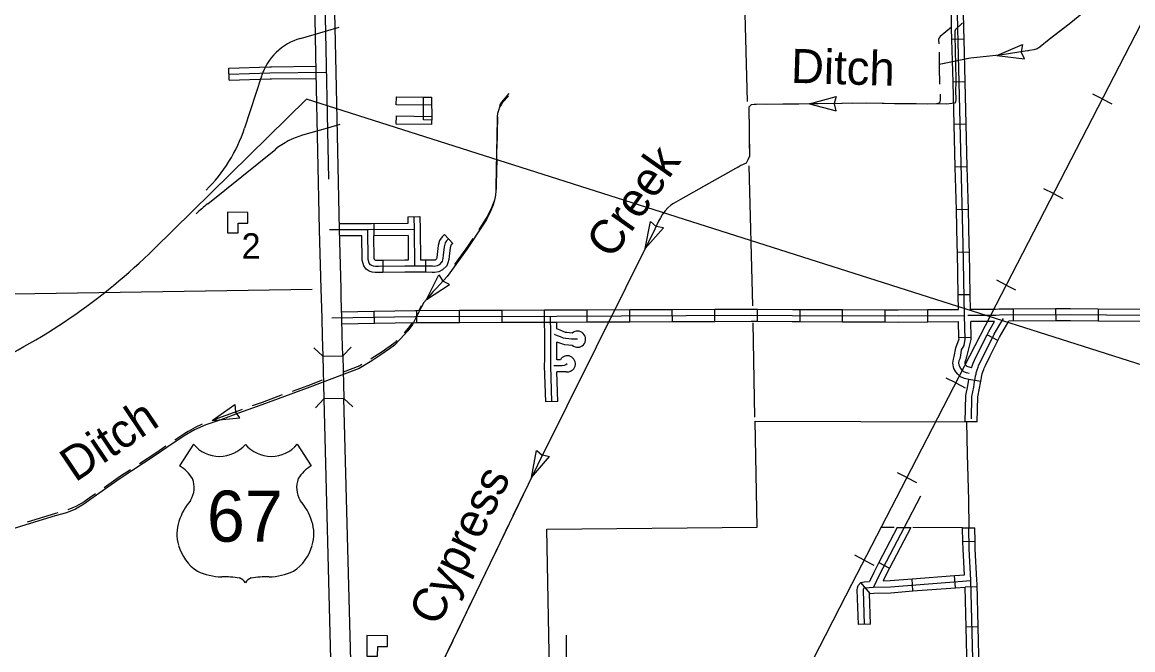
# Model space of a CAD drawing. Extents: x 1164457 to 1439835, y 1590918 to 1773502.
# Drawn here: x 1294282 to 1308056, y 1641151 to 1648927 of the extents above; entities that cross this region are included whole.
import ezdxf

# ---------------------------------------------------------------- set-up
doc = ezdxf.new("R2010")
doc.units = 0
for name, color, linetype in [('Level 10', 7, 'Continuous'), ('Level 15', 7, 'Continuous'), ('Level 22', 7, 'Continuous'), ('Level 32', 7, 'Continuous'), ('Level 34', 7, 'Continuous'), ('Level 37', 7, 'Continuous'), ('Level 40', 7, 'Continuous'), ('Level 43', 7, 'Continuous'), ('Level 45', 7, 'Continuous'), ('Level 5', 7, 'Continuous'), ('Level 58', 7, 'Continuous'), ('Level 6', 7, 'Continuous'), ('R_Draft', 7, 'Continuous')]:
    doc.layers.add(name, color=color, linetype=linetype)

msp = doc.modelspace()

# ---------------------------------------------------------------- linework, layer by layer
at = {"layer": 'Level 10'}
for points in [[(1298921, 1647904), (1298923, 1648004), (1299360, 1647997), (1299359, 1647897)], [(1299260, 1647999), (1299360, 1647997), (1299361, 1647714), (1299261, 1647716)], [(1298921, 1647665), (1298923, 1647765), (1299361, 1647758), (1299359, 1647658)]]:
    msp.add_lwpolyline(points, close=True, dxfattribs=at)
at = {"layer": 'Level 15'}
for points in [[(1297902, 1649429), (1297926, 1648305), (1297967, 1646353), (1297988, 1645622), (1297989, 1645504), (1297997, 1645260), (1298002, 1645032), (1298009, 1644787), (1298259, 1644793)], [(1298259, 1644793), (1298252, 1645039), (1298247, 1645267), (1298239, 1645510), (1298238, 1645628), (1298217, 1646359), (1298176, 1648310), (1298152, 1649429)], [(1298009, 1644787), (1298022, 1644259)], [(1298259, 1644793), (1298272, 1644266)], [(1298377, 1640272), (1298373, 1640395), (1298272, 1644266), (1298022, 1644259)], [(1298022, 1644259), (1298123, 1640389), (1298127, 1640265), (1298377, 1640272)]]:
    msp.add_lwpolyline(points, dxfattribs=at)
at = {"layer": 'Level 22'}
for p, q in [((1296407, 1643697), (1296234, 1643430)), ((1297694, 1643697), (1297867, 1643430))]:
    msp.add_line(p, q, dxfattribs=at)
for centre, radius, start, end in [((1296729, 1643968), 421, 220.075, 319.6701), ((1297371, 1643968), 421, 220.3299, 319.925), ((1296008, 1643041), 450, 30.7809, 59.7993), ((1298093, 1643041), 450, 120.2008, 149.2191), ((1296107, 1643160), 308, 328.8105, 21.2108), ((1297994, 1643160), 308, 158.7892, 211.1895), ((1296913, 1642528), 719, 138.9565, 162.6913), ((1297188, 1642528), 719, 17.3087, 41.0435), ((1296675, 1642587), 475, 160.9576, 197.3819), ((1297425, 1642587), 475, 342.6181, 19.0424), ((1296753, 1642588), 550, 195.1074, 237.1312), ((1297348, 1642588), 550, 302.8688, 344.8926), ((1296763, 1642761), 706, 244.0771, 269.5779), ((1296779, 1640762), 1293, 81.1942, 90.9539), ((1296941, 1641922), 124, 28.0342, 72.9864), ((1297160, 1641922), 124, 107.0136, 151.9658), ((1297321, 1640762), 1293, 89.0461, 98.8058), ((1297338, 1642761), 706, 270.4221, 295.9229)]:
    msp.add_arc(centre, radius, start, end, dxfattribs=at)
at = {"layer": 'Level 32'}
for p, q in [((1305964, 1648717), (1305814, 1648713)), ((1305977, 1648189), (1305827, 1648186)), ((1305991, 1647662), (1305841, 1647658)), ((1306004, 1647134), (1305854, 1647130)), ((1306018, 1646606), (1305868, 1646602)), ((1299065, 1646517), (1299215, 1646519)), ((1298643, 1646429), (1298645, 1646279)), ((1299521, 1646297), (1299622, 1646186)), ((1306031, 1646078), (1305881, 1646075)), ((1298755, 1645975), (1298757, 1645825)), ((1299285, 1645978), (1299283, 1645828)), ((1306040, 1645550), (1305890, 1645547)), ((1298651, 1645197), (1298648, 1645347)), ((1299178, 1645206), (1299177, 1645356)), ((1299706, 1645208), (1299705, 1645358)), ((1300234, 1645209), (1300233, 1645359)), ((1300762, 1645211), (1300761, 1645361)), ((1301290, 1645213), (1301289, 1645363)), ((1301818, 1645215), (1301817, 1645365)), ((1302346, 1645218), (1302345, 1645368)), ((1302874, 1645220), (1302873, 1645370)), ((1303401, 1645222), (1303402, 1645372)), ((1303929, 1645217), (1303930, 1645367)), ((1304457, 1645215), (1304458, 1645365)), ((1304985, 1645213), (1304986, 1645363)), ((1305514, 1645215), (1305513, 1645365)), ((1306571, 1645373), (1306572, 1645223)), ((1307099, 1645375), (1307100, 1645225)), ((1307628, 1645373), (1307627, 1645223)), ((1306051, 1645022), (1305901, 1645018)), ((1306384, 1644984), (1306250, 1645052)), ((1306172, 1644474), (1306024, 1644498)), ((1306128, 1643977), (1305978, 1643977)), ((1305136, 1642664), (1305305, 1642664)), ((1306100, 1642491), (1305950, 1642488)), ((1304908, 1642232), (1305041, 1642162)), ((1305330, 1641879), (1305319, 1642028)), ((1305857, 1641919), (1305845, 1642069)), ((1304801, 1641848), (1304683, 1641985)), ((1306126, 1641932), (1305976, 1641928)), ((1304804, 1641468), (1304654, 1641463)), ((1306139, 1641436), (1305989, 1641432))]:
    msp.add_line(p, q, dxfattribs=at)
for points in [[(1305977, 1644999), (1305969, 1645293), (1305954, 1646172), (1305885, 1648850), (1305848, 1650541)], [(1305814, 1648713), (1305810, 1648849), (1305802, 1649242)], [(1305964, 1648717), (1305960, 1648852), (1305952, 1649245)], [(1305827, 1648186), (1305814, 1648713)], [(1305977, 1648189), (1305964, 1648717)], [(1305841, 1647658), (1305827, 1648186)], [(1305991, 1647662), (1305977, 1648189)], [(1305854, 1647130), (1305841, 1647658)], [(1306004, 1647134), (1305991, 1647662)], [(1305868, 1646602), (1305854, 1647130)], [(1306018, 1646606), (1306004, 1647134)], [(1305881, 1646075), (1305879, 1646170), (1305868, 1646602)], [(1306031, 1646078), (1306029, 1646173), (1306018, 1646606)], [(1299065, 1646517), (1299066, 1646434)], [(1299140, 1646518), (1299143, 1646359), (1299147, 1645905)], [(1299215, 1646519), (1299218, 1646360), (1299221, 1645979)], [(1299143, 1646359), (1298569, 1646353), (1298092, 1646356)], [(1298614, 1646429), (1298569, 1646428), (1298215, 1646430)], [(1299571, 1646242), (1299546, 1646219), (1299528, 1646192), (1299517, 1646145), (1299503, 1646039), (1299498, 1645998), (1299491, 1645968), (1299484, 1645952), (1299452, 1645920), (1299427, 1645907), (1299392, 1645901), (1299369, 1645902), (1299147, 1645905), (1299027, 1645903), (1298701, 1645899), (1298664, 1645901), (1298641, 1645903), (1298617, 1645912), (1298601, 1645922), (1298587, 1645941), (1298574, 1645988), (1298569, 1646353)], [(1299066, 1646434), (1298614, 1646429)], [(1298495, 1646278), (1298219, 1646280)], [(1298757, 1645825), (1298700, 1645824), (1298659, 1645826), (1298624, 1645830), (1298584, 1645844), (1298550, 1645866), (1298518, 1645907), (1298499, 1645978), (1298495, 1646278)], [(1299068, 1646284), (1298645, 1646279)], [(1298755, 1645975), (1298702, 1645974), (1298670, 1645976), (1298659, 1645977), (1298654, 1645978), (1298649, 1645998), (1298645, 1646279)], [(1299068, 1646284), (1299071, 1645979)], [(1299521, 1646297), (1299489, 1646268), (1299459, 1646223), (1299443, 1646159), (1299429, 1646048), (1299424, 1646011), (1299420, 1645993), (1299408, 1645981), (1299404, 1645979), (1299387, 1645977), (1299371, 1645977), (1299221, 1645979)], [(1299622, 1646186), (1299603, 1646169), (1299598, 1646162), (1299591, 1646132), (1299577, 1646029), (1299572, 1645985), (1299563, 1645946), (1299548, 1645909), (1299497, 1645858), (1299450, 1645835), (1299397, 1645826), (1299368, 1645827), (1299283, 1645828)], [(1305890, 1645547), (1305881, 1646075)], [(1306040, 1645550), (1306031, 1646078)], [(1299071, 1645979), (1299026, 1645978), (1298755, 1645975)], [(1299283, 1645828), (1299147, 1645830), (1299027, 1645828), (1298757, 1645825)], [(1305893, 1645368), (1305890, 1645547)], [(1306043, 1645368), (1306040, 1645550)], [(1298244, 1645340), (1298648, 1645347)], [(1298648, 1645347), (1299162, 1645356), (1299177, 1645356)], [(1299177, 1645356), (1299705, 1645358)], [(1299705, 1645358), (1300233, 1645359)], [(1300233, 1645359), (1300761, 1645361)], [(1300761, 1645361), (1300908, 1645361), (1301289, 1645363)], [(1301289, 1645363), (1301817, 1645365)], [(1301817, 1645365), (1302345, 1645368)], [(1302345, 1645368), (1302873, 1645370)], [(1302873, 1645370), (1303323, 1645372), (1303402, 1645372)], [(1303402, 1645372), (1303834, 1645367), (1303930, 1645367)], [(1303930, 1645367), (1304458, 1645365)], [(1304458, 1645365), (1304986, 1645363)], [(1304986, 1645363), (1305148, 1645362), (1305513, 1645365)], [(1305513, 1645365), (1305893, 1645368)], [(1306571, 1645373), (1306401, 1645373), (1306354, 1645369), (1306292, 1645369), (1306043, 1645368)], [(1307099, 1645375), (1306571, 1645373)], [(1307628, 1645373), (1307282, 1645376), (1307099, 1645375)], [(1308156, 1645368), (1307628, 1645373)], [(1298122, 1645263), (1299162, 1645281), (1300908, 1645286), (1303322, 1645297), (1303833, 1645292), (1305148, 1645287), (1305967, 1645293)], [(1298248, 1645191), (1298651, 1645197)], [(1298651, 1645197), (1299163, 1645206), (1299178, 1645206)], [(1299178, 1645206), (1299706, 1645208)], [(1299706, 1645208), (1300234, 1645209)], [(1300234, 1645209), (1300762, 1645211)], [(1300762, 1645211), (1300908, 1645211), (1301290, 1645213)], [(1301290, 1645213), (1301818, 1645215)], [(1301818, 1645215), (1302346, 1645218)], [(1302346, 1645218), (1302874, 1645220)], [(1302874, 1645220), (1303322, 1645222), (1303401, 1645222)], [(1303401, 1645222), (1303833, 1645217), (1303929, 1645217)], [(1303929, 1645217), (1304457, 1645215)], [(1304457, 1645215), (1304985, 1645213)], [(1304985, 1645213), (1305148, 1645212), (1305514, 1645215)], [(1305514, 1645215), (1305896, 1645218)], [(1305901, 1645018), (1305896, 1645218)], [(1308622, 1645289), (1307282, 1645301), (1306404, 1645298), (1306358, 1645294), (1306292, 1645294), (1306011, 1645293)], [(1306343, 1645219), (1306292, 1645219), (1306046, 1645218)], [(1306051, 1645022), (1306046, 1645218)], [(1306054, 1644013), (1306060, 1644291), (1306084, 1644406), (1306095, 1644470), (1306102, 1644513), (1306107, 1644544), (1306112, 1644565), (1306116, 1644584), (1306125, 1644618), (1306137, 1644652), (1306144, 1644670), (1306161, 1644707), (1306220, 1644827), (1306339, 1645061), (1306397, 1645162), (1306452, 1645256)], [(1306250, 1645052), (1306273, 1645096), (1306343, 1645219)], [(1306384, 1644984), (1306405, 1645025), (1306462, 1645125), (1306520, 1645223)], [(1307100, 1645225), (1306520, 1645223)], [(1307627, 1645223), (1307282, 1645226), (1307100, 1645225)], [(1308155, 1645218), (1307627, 1645223)], [(1306024, 1644498), (1305969, 1644512), (1305921, 1644531), (1305886, 1644564), (1305862, 1644595), (1305837, 1644638), (1305825, 1644700), (1305832, 1644753), (1305843, 1644783), (1305861, 1644892), (1305902, 1645003), (1305901, 1645018)], [(1306028, 1644574), (1305992, 1644583), (1305962, 1644595), (1305942, 1644614), (1305925, 1644637), (1305908, 1644665), (1305901, 1644702), (1305905, 1644735), (1305915, 1644761), (1305924, 1644796), (1305933, 1644867), (1305965, 1644921), (1305977, 1644999)], [(1306055, 1644645), (1306014, 1644655), (1306003, 1644659), (1305998, 1644665), (1305987, 1644679), (1305979, 1644692), (1305977, 1644704), (1305979, 1644717), (1305987, 1644740), (1305997, 1644782), (1306052, 1644994), (1306051, 1645022)], [(1306055, 1644645), (1306067, 1644678), (1306075, 1644700), (1306094, 1644740), (1306153, 1644860), (1306250, 1645052)], [(1306180, 1644525), (1306180, 1644529), (1306185, 1644549), (1306189, 1644568), (1306196, 1644596), (1306207, 1644625), (1306213, 1644641), (1306229, 1644675), (1306288, 1644793), (1306384, 1644984)], [(1306128, 1643977), (1306135, 1644283), (1306157, 1644391), (1306169, 1644458), (1306176, 1644501), (1306180, 1644525)], [(1305978, 1643977), (1305985, 1644300), (1306010, 1644420), (1306024, 1644498)], [(1305221, 1642664), (1304910, 1642075), (1304840, 1641925)], [(1305136, 1642664), (1304908, 1642232)], [(1305305, 1642664), (1305041, 1642162)], [(1305950, 1642488), (1305946, 1642662), (1306096, 1642662)], [(1306094, 1640006), (1306090, 1640389), (1306049, 1642012), (1306027, 1642400), (1306021, 1642662)], [(1306100, 1642491), (1306096, 1642662)], [(1305970, 1642078), (1305952, 1642397), (1305950, 1642488)], [(1306126, 1641964), (1306124, 1642015), (1306102, 1642403), (1306100, 1642491)], [(1304908, 1642232), (1304843, 1642108), (1304791, 1641998)], [(1305041, 1642162), (1304977, 1642042), (1304960, 1642004)], [(1304960, 1642004), (1305048, 1642007), (1305319, 1642028)], [(1305319, 1642028), (1305845, 1642069)], [(1305845, 1642069), (1305970, 1642078)], [(1304654, 1641463), (1304640, 1641892), (1304644, 1641918), (1304651, 1641948), (1304683, 1641985), (1304723, 1641994), (1304791, 1641998)], [(1304729, 1641466), (1304715, 1641887), (1304718, 1641904), (1304720, 1641913), (1304723, 1641917), (1304733, 1641920), (1304840, 1641925), (1305052, 1641932), (1306049, 1642009)], [(1305330, 1641879), (1305857, 1641919)], [(1305857, 1641919), (1305976, 1641928)], [(1305989, 1641432), (1305976, 1641928)], [(1306139, 1641436), (1306126, 1641964)], [(1304804, 1641468), (1304792, 1641847), (1304801, 1641848)], [(1304801, 1641848), (1304843, 1641850), (1305056, 1641857), (1305330, 1641879)], [(1306002, 1640904), (1305989, 1641432)], [(1306152, 1640908), (1306139, 1641436)]]:
    msp.add_lwpolyline(points, dxfattribs=at)
at = {"layer": 'Level 34'}
for points in [[(1305996, 1643977), (1306004, 1643576), (1306020, 1643005), (1306021, 1642662)], [(1305425, 1643053), (1305221, 1642664)], [(1301027, 1641330), (1301028, 1640940), (1301032, 1640782), (1301042, 1640656), (1301042, 1640568), (1301045, 1640474), (1301042, 1640400), (1301038, 1640306), (1301035, 1640180), (1301038, 1640110), (1301042, 1640092), (1301056, 1640068), (1301076, 1640050), (1301099, 1640045), (1302059, 1640056), (1302175, 1640059), (1302222, 1640066), (1302255, 1640071), (1302294, 1640079)]]:
    msp.add_lwpolyline(points, dxfattribs=at)
at = {"layer": 'Level 37'}
for points in [[(1298009, 1644787), (1297900, 1644890)], [(1298362, 1644902), (1298259, 1644793)], [(1297919, 1644150), (1298022, 1644259)], [(1298272, 1644266), (1298381, 1644162)]]:
    msp.add_lwpolyline(points, dxfattribs=at)
at = {"layer": 'Level 40'}
for p, q in [((1307677, 1647976), (1307560, 1648036)), ((1307677, 1647976), (1307795, 1647915)), ((1307072, 1646803), (1306954, 1646863)), ((1307072, 1646803), (1307189, 1646742)), ((1306486, 1645669), (1306369, 1645730)), ((1306486, 1645669), (1306603, 1645609)), ((1305860, 1644457), (1305743, 1644518)), ((1305860, 1644457), (1305978, 1644397)), ((1305255, 1643284), (1305138, 1643345)), ((1305255, 1643284), (1305372, 1643223)), ((1304726, 1642261), (1304608, 1642322)), ((1304726, 1642261), (1304843, 1642200))]:
    msp.add_line(p, q, dxfattribs=at)
for points in [[(1308885, 1650314), (1306292, 1645294), (1306097, 1644916), (1305370, 1643507), (1304569, 1641958), (1304420, 1641671)], [(1308885, 1650314), (1306292, 1645294), (1306097, 1644916), (1305370, 1643507), (1304569, 1641958), (1304420, 1641671)], [(1304420, 1641671), (1304337, 1641509), (1304241, 1641324), (1303819, 1640506), (1303537, 1639968), (1303419, 1639735), (1303151, 1639213), (1302887, 1638707), (1301917, 1636833), (1301040, 1635131), (1300739, 1634544), (1300431, 1633947), (1300340, 1633776)], [(1304420, 1641671), (1304337, 1641509), (1304241, 1641324), (1303819, 1640506)]]:
    msp.add_lwpolyline(points, dxfattribs=at)
at = {"layer": 'Level 43'}
for p, q in [((1306372, 1648516), (1306688, 1648650)), ((1306688, 1648650), (1306674, 1648560)), ((1306372, 1648516), (1306713, 1648472)), ((1306713, 1648472), (1306674, 1648560)), ((1304047, 1647914), (1304377, 1648006)), ((1304377, 1648006), (1304354, 1647918)), ((1304047, 1647914), (1304379, 1647829)), ((1304379, 1647829), (1304355, 1647917)), ((1302008, 1646121), (1302076, 1646458)), ((1302074, 1646457), (1302144, 1646397)), ((1302008, 1646121), (1302235, 1646379)), ((1302235, 1646380), (1302145, 1646397)), ((1299295, 1645490), (1299451, 1645797)), ((1299451, 1645797), (1299500, 1645720)), ((1299295, 1645490), (1299582, 1645677)), ((1299582, 1645677), (1299501, 1645719)), ((1296640, 1643990), (1296920, 1644190)), ((1296920, 1644190), (1296928, 1644099)), ((1296982, 1644023), (1296929, 1644098)), ((1296640, 1643990), (1296982, 1644023)), ((1300598, 1643284), (1300662, 1643621)), ((1300598, 1643284), (1300822, 1643544)), ((1300664, 1643621), (1300733, 1643561)), ((1300823, 1643542), (1300734, 1643560))]:
    msp.add_line(p, q, dxfattribs=at)
for points in [[(1308402, 1649511), (1308080, 1649390), (1307809, 1649302), (1307721, 1649257), (1307641, 1649192), (1307446, 1649046), (1307267, 1648904), (1307018, 1648714), (1306909, 1648621), (1306872, 1648597), (1306829, 1648584), (1306720, 1648568), (1306437, 1648523), (1306043, 1648481), (1305655, 1648404)], [(1305946, 1648920), (1305919, 1648896), (1305869, 1648850), (1305857, 1648835), (1305851, 1648814), (1305854, 1648527), (1305856, 1648444), (1305862, 1648180), (1305859, 1648079), (1305861, 1647970), (1305857, 1647940), (1305845, 1647925), (1305814, 1647919), (1305751, 1647913), (1305146, 1647915), (1304749, 1647922), (1303858, 1647911), (1303359, 1647906), (1303323, 1647903), (1303308, 1647888), (1303295, 1647876), (1303301, 1647266), (1303284, 1647222), (1303261, 1647180), (1303197, 1647151), (1302446, 1646731), (1302362, 1646681), (1302327, 1646658), (1302289, 1646627), (1302256, 1646590), (1302223, 1646547), (1302199, 1646501), (1302175, 1646462), (1302127, 1646361), (1300673, 1643440)], [(1305810, 1648867), (1305666, 1648750), (1305654, 1648735), (1305648, 1648714), (1305649, 1648661)], [(1307201, 1648853), (1307018, 1648714), (1306909, 1648621), (1306890, 1648608)], [(1305653, 1648555), (1305654, 1648454), (1305656, 1648371), (1305661, 1648159)], [(1306241, 1648502), (1306043, 1648481), (1305970, 1648467)], [(1306764, 1648574), (1306720, 1648568), (1306437, 1648523), (1306372, 1648516)], [(1305720, 1648417), (1305655, 1648404)], [(1300313, 1648012), (1300241, 1647931), (1300222, 1647905), (1300202, 1647873), (1300188, 1647833), (1300179, 1647794), (1300174, 1647759), (1300171, 1647730), (1300157, 1646889), (1300155, 1646837), (1300151, 1646785), (1300141, 1646722), (1300123, 1646662), (1300096, 1646595), (1300071, 1646541), (1300041, 1646481), (1299995, 1646412), (1299800, 1646119), (1299551, 1645775), (1299466, 1645682), (1299416, 1645629), (1299376, 1645584), (1299325, 1645526), (1299263, 1645452), (1299230, 1645391), (1299160, 1645256), (1299122, 1645182), (1299065, 1645103), (1299020, 1645052), (1298972, 1645001), (1298900, 1644927), (1298839, 1644880), (1298729, 1644805), (1298619, 1644732), (1298463, 1644638), (1297817, 1644393), (1297253, 1644185), (1296963, 1644083), (1296744, 1644001), (1296560, 1643936), (1296421, 1643875), (1296293, 1643800), (1296077, 1643658), (1295932, 1643557), (1295497, 1643271)], [(1300318, 1648043), (1300247, 1647961), (1300228, 1647935), (1300208, 1647904), (1300201, 1647885)], [(1305666, 1648036), (1305668, 1647967), (1305664, 1647936), (1305652, 1647922), (1305621, 1647915), (1305515, 1647913)], [(1303387, 1647907), (1303359, 1647906), (1303323, 1647903), (1303308, 1647888), (1303295, 1647876), (1303298, 1647583)], [(1303717, 1647910), (1303519, 1647908)], [(1303915, 1647912), (1303858, 1647911), (1303717, 1647910)], [(1304443, 1647918), (1304047, 1647914)], [(1304971, 1647918), (1304749, 1647922), (1304575, 1647920)], [(1305368, 1647914), (1305146, 1647915), (1305103, 1647916)], [(1300177, 1647756), (1300170, 1647360)], [(1303299, 1647451), (1303301, 1647266), (1303284, 1647222), (1303261, 1647180), (1303197, 1647151), (1303157, 1647128)], [(1300168, 1647228), (1300162, 1646920), (1300161, 1646868), (1300158, 1646832)], [(1303042, 1647064), (1302696, 1646871)], [(1302581, 1646806), (1302446, 1646731), (1302362, 1646681), (1302327, 1646658), (1302289, 1646627), (1302256, 1646590), (1302254, 1646587)], [(1300131, 1646703), (1300128, 1646693), (1300102, 1646626), (1300076, 1646572), (1300046, 1646511), (1300001, 1646442), (1299944, 1646356)], [(1302184, 1646476), (1302175, 1646462), (1302127, 1646361), (1302008, 1646121)], [(1299871, 1646247), (1299806, 1646149), (1299642, 1645923)], [(1301949, 1646003), (1301861, 1645826)], [(1299559, 1645786), (1299551, 1645775), (1299466, 1645682), (1299416, 1645629), (1299376, 1645584), (1299325, 1645526), (1299295, 1645490)], [(1301861, 1645826), (1301772, 1645649)], [(1301714, 1645530), (1301631, 1645364)], [(1299230, 1645411), (1299202, 1645356)], [(1299123, 1645206), (1299071, 1645134), (1299025, 1645083), (1299020, 1645077)], [(1301556, 1645214), (1301537, 1645176)], [(1298929, 1644982), (1298906, 1644958), (1298844, 1644911), (1298735, 1644836), (1298624, 1644762), (1298607, 1644752)], [(1301478, 1645058), (1301302, 1644703)], [(1298494, 1644684), (1298468, 1644668), (1298264, 1644591)], [(1301243, 1644585), (1301067, 1644231)], [(1298003, 1644492), (1297823, 1644423), (1297632, 1644353)], [(1297508, 1644308), (1297259, 1644216), (1297136, 1644172)], [(1297011, 1644128), (1296969, 1644113), (1296749, 1644031), (1296639, 1643993)], [(1301008, 1644112), (1300831, 1643758)], [(1296340, 1643855), (1296298, 1643831), (1296174, 1643749)], [(1296516, 1643945), (1296427, 1643906), (1296340, 1643855)], [(1296064, 1643675), (1295938, 1643587), (1295735, 1643454)], [(1300773, 1643640), (1300673, 1643440), (1300598, 1643284)], [(1300673, 1643440), (1299269, 1640531)], [(1295497, 1643271), (1295234, 1643085), (1295106, 1642997), (1295046, 1642953), (1294942, 1642894), (1294831, 1642848), (1294690, 1642809), (1292844, 1642246), (1292603, 1642180), (1292530, 1642151), (1292471, 1642112), (1291148, 1640567)], [(1295625, 1643382), (1295502, 1643302), (1295299, 1643157)], [(1300541, 1643165), (1300455, 1642987)], [(1295191, 1643082), (1295112, 1643028), (1295052, 1642984), (1294947, 1642924), (1294849, 1642884)], [(1300455, 1642987), (1300369, 1642809)], [(1294723, 1642847), (1294696, 1642840), (1294344, 1642732)], [(1300311, 1642690), (1300139, 1642333)], [(1300082, 1642214), (1299909, 1641858)], [(1299852, 1641739), (1299680, 1641382)], [(1299623, 1641263), (1299450, 1640907)]]:
    msp.add_lwpolyline(points, dxfattribs=at)
at = {"layer": 'Level 45'}
for p, q in [((1296851, 1648208), (1296845, 1648358)), ((1300927, 1644227), (1300777, 1644223))]:
    msp.add_line(p, q, dxfattribs=at)
for points in [[(1296845, 1648358), (1297352, 1648376), (1297375, 1648376)], [(1297375, 1648376), (1297924, 1648381)], [(1296848, 1648283), (1297354, 1648301), (1298051, 1648307)], [(1297376, 1648226), (1297927, 1648231)], [(1296851, 1648208), (1297356, 1648226), (1297376, 1648226)], [(1300763, 1644753), (1300765, 1645063), (1300762, 1645211)], [(1300852, 1644225), (1300837, 1644669), (1300840, 1645064), (1300835, 1645286)], [(1300914, 1645128), (1300912, 1645211)], [(1301170, 1644999), (1301143, 1645001), (1301123, 1644999), (1301096, 1644999), (1301062, 1645002), (1301026, 1645006), (1300997, 1645012), (1300958, 1645027), (1300923, 1645041), (1300883, 1645059)], [(1301104, 1645074), (1301069, 1645077), (1301038, 1645080), (1301019, 1645084), (1300985, 1645097), (1300953, 1645110), (1300914, 1645128)], [(1300913, 1644744), (1300914, 1644964)], [(1301105, 1644923), (1301056, 1644927), (1301014, 1644931), (1300975, 1644940), (1300914, 1644964)], [(1300777, 1644223), (1300762, 1644668), (1300763, 1644753)], [(1301043, 1644694), (1301024, 1644681), (1301005, 1644672), (1300979, 1644670), (1300876, 1644669)], [(1300957, 1644745), (1300913, 1644744)], [(1301027, 1644595), (1300915, 1644594)], [(1300927, 1644227), (1300915, 1644594)]]:
    msp.add_lwpolyline(points, dxfattribs=at)
for centre, start, end in [((1301170, 1644999), 229.3471, 131.714), ((1301043, 1644694), 260.811, 149.2906)]:
    msp.add_arc(centre, 100, start, end, dxfattribs=at)
at = {"layer": 'Level 5'}
for points in [[(1303277, 1647944), (1303212, 1650430)], [(1303343, 1645411), (1303297, 1647148)], [(1297879, 1645616), (1292846, 1645537)], [(1303370, 1644033), (1303348, 1645201)]]:
    msp.add_lwpolyline(points, dxfattribs=at)
at = {"layer": 'Level 58'}
for points in [[(1296828, 1646573), (1296827, 1646319), (1296961, 1646318), (1296962, 1646438), (1297082, 1646438), (1297082, 1646571)], [(1298558, 1641326), (1298556, 1641072), (1298690, 1641071), (1298691, 1641191), (1298811, 1641190), (1298812, 1641324)]]:
    msp.add_lwpolyline(points, close=True, dxfattribs=at)
at = {"layer": 'Level 6'}
for points in [[(1303396, 1642669), (1303371, 1643985), (1305996, 1643977)], [(1298384, 1640003), (1299485, 1640009), (1300839, 1640020), (1300789, 1642644), (1303396, 1642669)], [(1305097, 1642665), (1304935, 1642665)], [(1305946, 1642662), (1305327, 1642664)]]:
    msp.add_lwpolyline(points, dxfattribs=at)
at = {"layer": 'R_Draft'}
for p, q in [((1298037, 1649195), (1298080, 1646983)), ((1297732, 1648726), (1298044, 1648816)), ((1298044, 1648816), (1298214, 1648865)), ((1297250, 1648260), (1297039, 1647614)), ((1297809, 1647974), (1295919, 1646118)), ((1375114, 1623387), (1297809, 1647974)), ((1298068, 1647616), (1297758, 1647527)), ((1298223, 1647661), (1298068, 1647616)), ((1296583, 1646677), (1297426, 1647354))]:
    msp.add_line(p, q, dxfattribs=at)
for centre, radius, start, end in [((1297931, 1648038), 716, 106.1214, 161.8881), ((1295224, 1648208), 1910, 314.4714, 341.8881), ((1298023, 1646609), 955, 106.1214, 128.7631), ((1297778, 1645188), 1910, 128.7631, 134.4714), ((1290567, 1651569), 7639, 294.2214, 314.4714)]:
    msp.add_arc(centre, radius, start, end, dxfattribs=at)

# ---------------------------------------------------------------- texts
at = {"layer": 'Level 22'}
msp.add_text('67', height=633, dxfattribs=at).set_placement((1296573, 1642490))
at = {"layer": 'Level 43'}
for s, rotation, p in [('Ditch', 358.2575, (1303813, 1648177)), ('Creek', 54.8528, (1301595, 1645975)), ('Ditch', 33.9487, (1294939, 1643219)), ('Cypress', 64.0274, (1299440, 1641426))]:
    msp.add_text(s, height=422, rotation=rotation, dxfattribs=at).set_placement(p)
at = {"layer": 'Level 58'}
msp.add_text('2', height=317, dxfattribs=at).set_placement((1297003, 1645995))

doc.saveas('drawing.dxf')
